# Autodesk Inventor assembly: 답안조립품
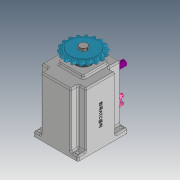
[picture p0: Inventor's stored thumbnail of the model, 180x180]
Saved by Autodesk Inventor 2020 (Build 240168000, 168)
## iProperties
Created: 2022-01
Part Number: 답안조립품
Document SubType Name: Assembly
Designer: user
Author: user
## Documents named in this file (16)
- C:\Users\user\Desktop\720112V1002\답안조립품.iam
- C:\Users\user\Desktop\720112V1002\멈춤나사 M3.ipt
- C:\Users\user\Desktop\720112V1002\메인 축.ipt
- C:\Users\user\Desktop\720112V1002\베어링 608.ipt
- C:\Users\user\Desktop\720112V1002\베어링 6003.ipt
- C:\Users\user\Desktop\720112V1002\본체.ipt
- C:\Users\user\Desktop\720112V1002\볼트 M4 x 10.ipt
- C:\Users\user\Desktop\720112V1002\부시.ipt
- C:\Users\user\Desktop\720112V1002\상부 캡.ipt
- C:\Users\user\Desktop\720112V1002\서브 축.ipt
- C:\Users\user\Desktop\720112V1002\스프로킷.ipt
- C:\Users\user\Desktop\720112V1002\슬라이더.ipt
- C:\Users\user\Desktop\720112V1002\오일 실 8 x 22 x 7.ipt
- C:\Users\user\Desktop\720112V1002\오일 실 17 x 32 x 8.ipt
- C:\Users\user\Desktop\720112V1002\커버.ipt
- C:\Users\user\Desktop\720112V1002\키 5 x 5.ipt
